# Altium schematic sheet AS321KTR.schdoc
size 127 x 101 mm
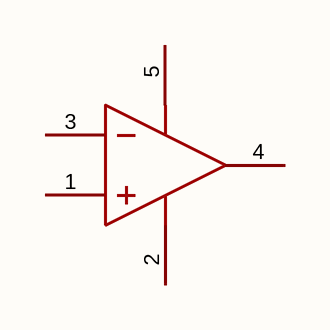
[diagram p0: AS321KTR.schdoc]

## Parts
U?  as321ktr  [SOT-23-5_L2.9-W1.6-P0.95-LS2.8-BL]  (value not drawn)

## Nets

Not connected (* = marked no-connect by the designer): U? 1(+IN) 2(V-) 3(-IN) 4(OUT) 5(V+)

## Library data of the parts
U? = as321ktr: 放大器数:2;轨到轨:-;增益带宽积(GBW):-;输入失调电压(Vos):11mV;压摆率(SR):-;输入偏置电流(Ib):250nA;; Manufacturer: TECH PUBLIC(台舟); AddInBom: yes; ModelId: 018c57e721114987ae90467fe9f1d259; ModelTransform: 114.96,110.236,0,0,0,0,0,0,0; Number of Channels: 2; Maximum Power Supply Range (Vdd-Vss): 36V; Vos - Input Offset Voltage: 11mV; Input Offset Voltage Drift(Vos TC): 7uV/℃; Ib - Input Bias Current: 250nA; Input Offset Current(Ios): 2nA; Common Mode Rejection Ratio(CMRR): 80dB; Input offset current drift(Ios TC): 10pA/℃; Quiescent Current: 700uA; Output Current: 20mA; Single supply: 3V~36V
